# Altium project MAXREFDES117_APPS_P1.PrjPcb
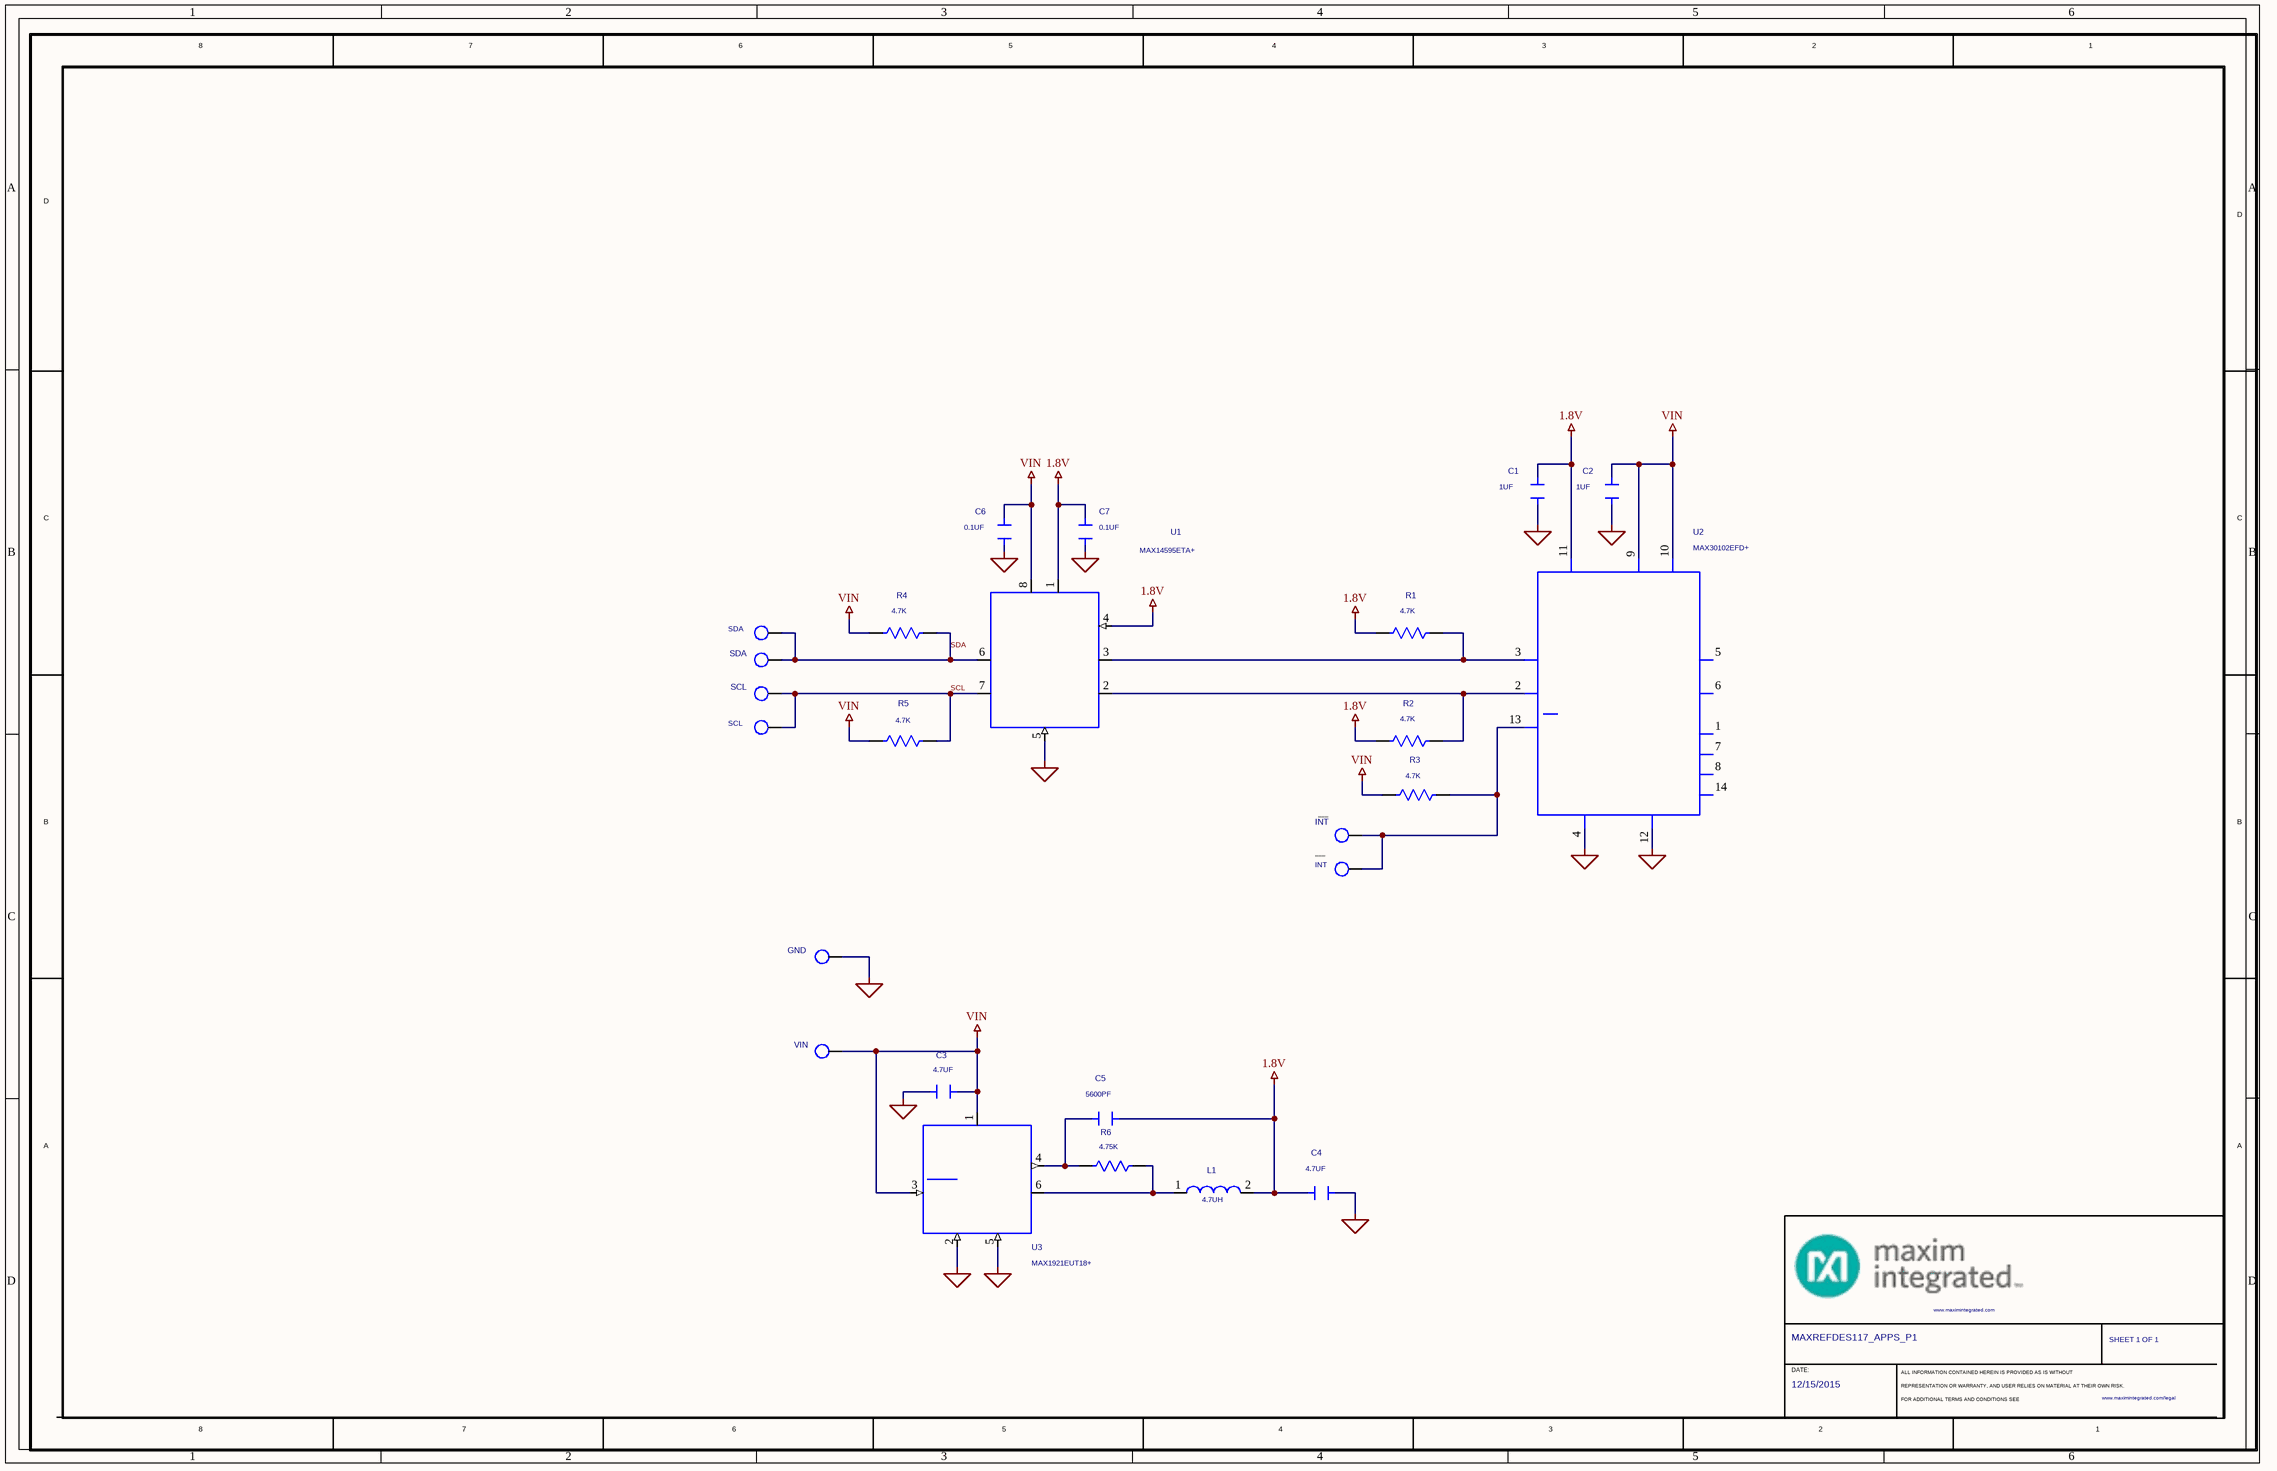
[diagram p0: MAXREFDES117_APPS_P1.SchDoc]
1 sheet, 26 parts. Net scope: global (net labels, ports and power ports of the same name join across sheets).

## Sheet MAXREFDES117_APPS_P1.SchDoc
size 424 x 274 mm

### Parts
*  CUSTOM_TXT_CDS21: SHEET 1 OF 1  PROJECT_TITLE: MAXREFDES117_APPS_P1  DATE: 12/15/2015  (hidden comment: MAXIM_B_SIZE_CF)  (graphical)
C1  1UF  [0402]
C2  1UF  [0402]
C3  4.7UF  [0402]
C4  4.7UF  [0402]
C5  5600PF  [0402]
C6  0.1UF  [0402]
C7  0.1UF  [0402]
GND  N/A  [EK_TP_PEDGE]  (value not drawn)
INT  N/A  [EK_TP_PEDGE]  (value not drawn)
L1  4.7UH  [0603]
R1  4.7K  [0402]
R2  4.7K  [0402]
R3  4.7K  [0402]
R4  4.7K  [0402]
R5  4.7K  [0402]
R6  4.75K  [0402]
SCL  N/A  [EK_TP_PEDGE]  (value not drawn)
SDA  N/A  [EK_TP_PEDGE]  (value not drawn)
U1  MAX14595ETA+  [MAXIM_90-0349]
U2  MAX30102EFD+  [PSON80P560X330X165-14M]
U3  MAX1921EUT18+  [SOT95P280X145-6M]
VIN  N/A  [EK_TP_PEDGE]  (value not drawn)
X1  COMMENTS: SDA  [EK_TP_PEDGE]  (hidden comment: N/A)
X2  COMMENTS: SCL  [EK_TP_PEDGE]  (hidden comment: N/A)
X3  COMMENTS: INT  [EK_TP_PEDGE]  (hidden comment: N/A)

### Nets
1.8V: C1.2 C4.1 C5.2 C7.2 L1.2 R1.1 R2.1 U1.1(VL) U1.4(/TS) U2.11(VDD)
GND_SIGNAL: C1.1 C2.1 C3.1 C4.2 C6.1 C7.1 GND.1(TP1) U1.5(GND) U2.4(PGND) U2.12(GND) U3.2(AGND) U3.5(PGND)
VIN: C2.2 C3.2 C6.2 R3.1 R4.1 R5.1 U1.8(VCC) U2.9(VLED+_1) U2.10(VLED+_2) U3.1(IN) U3.3(/SHDN) VIN.1(TP1)
SCL: R5.2 SCL.1(TP1) U1.7(IOVCC2) X2.1(TP1)
SDA: R4.2 SDA.1(TP1) U1.6(IOVCC1) X1.1(TP1)
NetC5_1: C5.1 R6.1 U3.4(OUT)
NetINT_1: INT.1(TP1) R3.2 U2.13(/INT) X3.1(TP1)
NetL1_1: L1.1 R6.2 U3.6(LX)
NetR1_2: R1.2 U1.3(IOVL1) U2.3(SDA)
NetR2_2: R2.2 U1.2(IOVL2) U2.2(SCL)

Not connected (* = marked no-connect by the designer): U2 1(NC_1) 5(R_DRV) 6(IR_DRV) 7(NC_2) 8(NC_3) 14(NC_4)

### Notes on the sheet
- (near INT) –––
- –––

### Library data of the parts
* = MAXIM_B_SIZE_CF: OriginalSymbolOrigin: (175,5230); COMMENT_BODY: TRUE; Page Number: 1
C1 C2 = CAP_NP#1: CAP; SMT (0402); 1UF; 10%; 10V; X5R; CERAMIC; MANUFACTURER: VENKEL LTD.;MURATA; OriginalSymbolOrigin: (-50,50); PACK_TYPE: 0402CAP; MAXINV: 20-0001U-33; CAP: 1.00E-06; DRAWING: @MAXREFDES117_APPS_P1.MAXREFDES117_APPS_P1(SCH_1):PAGE2; PHYS_PAGE: 1; VER: 2; TEMP_RANGE: -55 DEGC TO +85 DEGC; VLOG_PARAM01: CAP:INTEGER
C3 C4 = CAP_NP: CAP; SMT (0402); 4.7UF; 20%; 4V; X5R; CERAMIC; MANUFACTURER: KEMET;MURATA;MURATA; OriginalSymbolOrigin: (-50,50); PACK_TYPE: 0402CAP; MAXINV: 20-004U7-B65; CAP: 4.70E-06; DRAWING: @MAXREFDES117_APPS_P1.MAXREFDES117_APPS_P1(SCH_1):PAGE2; PHYS_PAGE: 1; TEMP_RANGE: -55 DEGC TO +85 DEGC; VLOG_PARAM01: CAP:INTEGER
C5 = CAP_NP: CAP; SMT (0402); 5600PF; 10%; 25V; X7R; CERAMIC; MANUFACTURER: VENKEL LTD;MURATA;MURATA; OriginalSymbolOrigin: (-50,50); PACK_TYPE: 0402CAP; MAXINV: 20-5600P-12; CAP: 5.60E-09; DRAWING: @MAXREFDES117_APPS_P1.MAXREFDES117_APPS_P1(SCH_1):PAGE2; PHYS_PAGE: 1; TEMP_RANGE: -55 DEGC TO +125 DEGC; VLOG_PARAM01: CAP:INTEGER
C6 C7 = CAP_NP#1: CAP; SMT (0402); 0.1UF; 10%; 16V; X7R; CERAMIC; MANUFACTURER: TDK;AMERICAN TECHNICAL CERAMICS;AVK;VENKEL LTD.;SAMSUNG ELECTRONICS;MURATA;TDK;YAGEO PHICOMP;TAIYO YUDEN;SAMSUNG ELECTRONICS; OriginalSymbolOrigin: (-50,50); PACK_TYPE: 0402CAP; MAXINV: 20-000U1-L1A; CAP: 1.00E-07; DRAWING: @MAXREFDES117_APPS_P1.MAXREFDES117_APPS_P1(SCH_1):PAGE2; PHYS_PAGE: 1; VER: 2; TEMP_RANGE: -55 DEGC TO +125 DEGC; VLOG_PARAM01: CAP:INTEGER
GND INT SCL SDA VIN X1-X3 = EVKIT_TP: TEST POINT; PAD DIMENSION =2.00MM X 2.00MM X ROUND BASE DIA=1.00 MM; BOARD HOLE= 1.02MM; OriginalSymbolOrigin: (-125,50); DRAWING: @MAXREFDES117_APPS_P1.MAXREFDES117_APPS_P1(SCH_1):PAGE2; PHYS_PAGE: 1
L1 = INDUCT: INDUCTOR; SMT (0603); MAGNETICALLY SHIELDED; 4.7UH; TOL=+/-20%; 0.5A; MANUFACTURER: TDK; OriginalSymbolOrigin: (-100,50); MAXINV: 50-004U7-0HR; DRAWING: @MAXREFDES117_APPS_P1.MAXREFDES117_APPS_P1(SCH_1):PAGE2; PHYS_PAGE: 1; TOLERANCE: 20%; TEMP_RANGE: -40 DEGC TO +105 DEGC
R1-R5 = RES_SMD: RES; SMT (0402); 4.7K; 1%; +/-100PPM/DEGC; 0.1000W; MANUFACTURER: PANASONIC; OriginalSymbolOrigin: (-75,50); PACK_TYPE: 0402RES; MAXINV: 80-004K7-18; DRAWING: @MAXREFDES117_APPS_P1.MAXREFDES117_APPS_P1(SCH_1):PAGE2; PHYS_PAGE: 1; POWER_RATING: 0.10W; RES: 4.70E03; VER: 2; TEMP_RANGE: -55 DEGC TO +155 DEGC; VLOG_PARAM01: RES:INTEGER
R6 = RES_SMD: RES; SMT (0402); 4.75K; 1%; +/-100PPM/DEGC; 0.0630W; MANUFACTURER: VISHAY DALE; OriginalSymbolOrigin: (-75,50); PACK_TYPE: 0402RES; MAXINV: 80-04K75-23; DRAWING: @MAXREFDES117_APPS_P1.MAXREFDES117_APPS_P1(SCH_1):PAGE2; PHYS_PAGE: 1; POWER_RATING: 0.0625W; RES: 4.75E03; VER: 2; TEMP_RANGE: -55 DEGC TO +155 DEGC; VLOG_PARAM01: RES:INTEGER
U1 = MAX14595: IC; TRANS; LOW-POWER DUAL-CHANNEL LOGIC-LEVEL TRANSLATOR; TDFN8 2X2; MANUFACTURER: MAXIM; OriginalSymbolOrigin: (-200,250); MAXINV: 10-MAX14595ETA-T; DRAWING: @MAXREFDES117_APPS_P1.MAXREFDES117_APPS_P1(SCH_1):PAGE2; PHYS_PAGE: 1; VOLTAGE_RATING: +1.65V TO +5.5V; TEMP_RANGE: -40 DEGC TO +85 DEGC
U2 = MAX30102: MODULE; SNSR; HIGH-SENSITIVITY PULSE OXIMETER AND HEART-RATE SENSOR FOR WEARABLE; SMT 5.6MM X 3.3MM; MANUFACTURER: MAXIM; OriginalSymbolOrigin: (-350,525); PACK_TYPE: OLGA14; MAXINV: 10-MAX30102EFD-00; DRAWING: @MAXREFDES117_APPS_P1.MAXREFDES117_APPS_P1(SCH_1):PAGE2; PHYS_PAGE: 1; VER: 3; VOLTAGE_RATING: +1.8V AND +5V; TEMP_RANGE: -40 DEGC TO +85 DEGC
U3 = MAX1921: IC; CONV; LOW-VOLTAGE; 400MA STEP-DOWN DC-DC CONVERTER; SOT23-6; MANUFACTURER: MAXIM; OriginalSymbolOrigin: (-200,200); MAXINV: 10-MAX1921EUT18-U; DRAWING: @MAXREFDES117_APPS_P1.MAXREFDES117_APPS_P1(SCH_1):PAGE2; PHYS_PAGE: 1; VOLTAGE_RATING: +1.8V; TEMP_RANGE: -40 DEGC TO +85 DEGC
